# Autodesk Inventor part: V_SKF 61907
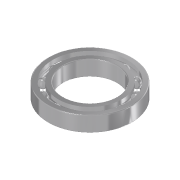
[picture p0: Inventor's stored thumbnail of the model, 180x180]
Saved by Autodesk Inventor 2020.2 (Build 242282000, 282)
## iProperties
+MSCProtocol1+ProtocolID: P00060228140304281
+MSCProtocol2+Protocol: P00060228140304281<@PID>[Version]<@EL>Version=2.2<@EL>[Files]<@EL>DataFile=SpiData|n024630a<@EL>[Synchronize]<@EL>ChangedVars=<@EL>[Calc]<@EL>DDmin=<@EL>DDmax=<
Manager: www.cadconsulting.pl
Company: Fabian Stasiak CAD Consulting
Shininess: 20.0
Length Units: 11269
Angle Units: 11279
Time Units: 11290
Mass Units: 11283
Length Display Precision: 3
Angle Display Precision: 2
Created: 2001-01
Part Number: V_SKF 61907
Material: Stal
Document SubType Name: Modeling
Description: Łożysko SKF 61907
Stock Number: SKF 61907
Project: Przekładnia X51
Designer: F.Stasiak
Density: 7.85 g/cm^3
Appearance: Chrom
Density: 7.86
Volumn: 47.63899704516156
Area: 199.2492810037185
PropertySet Name: Model Information
Control State: 0
Master: False
Checked Out: False
BOM1: Łożysko
BOM2: SKF 61907
Author: F.Stasiak
Subject: Zbiór ćwiczeń. Autodesk Inventor 2020. Kurs podstawowy
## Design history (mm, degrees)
node "Sketch1"
node "WorkPoint1"
sketch "Sketch2"
  geometry: L1 (17.5, 10)-(27.5, 10); L2 (17.5, 0)-(17.5, 10); L3 (27.5, 0)-(17.5, 0); L4 (27.5, 10)-(27.5, 0); L5 (0, 0)-(0, 20); L6 (0, 0)-(0, 20); L7 (-3.6, 0)-(46.8, 0) reference
  constraints: 12 end point, 3 vertical, 2 horizontal, 1 collinear, 1 other
  dimensions: "d1" = 35 diameter of L1.start L5 (= prf_d); "d3" = 55 diameter of L1.end L5 (= prf_dd); "d5" = 10 distance of L2.start L1.start (= msp_mdtd2)
revolve "RevolutionFull1" sketch "Sketch2" stored, may be unused: angle "d6" = 360 deg
node "WorkAxis1"
node "WorkPlane3"
sketch "Sketch3"
  geometry: L1 (24.3, 10)-(24.3, 7.4); L2 (20.7, 10)-(24.3, 10); L3 (20.7, 7.4)-(20.7, 10); L4 (20.7, 0)-(20.7, 2.6); L5 (24.3, 0)-(20.7, 0); L6 (24.3, 2.6)-(24.3, 0); L7 (27.5, 0)-(-27.5, 0) reference; L8 (27.5, 10)-(-27.5, 10) reference; L9 (0, -42.29)-(0, 61.29); L10 (0, 92.365)-(0, -52.649) reference; A1 r 3 centre (22.5, 5) between (24.3, 2.6) and (24.3, 7.4); A2 r 3 centre (22.5, 5) between (20.7, 7.4) and (20.7, 2.6)
  constraints: 14 end point, 4 collinear, 4 point on circle, 4 vertical, 2 centre point, 2 concentric, 2 horizontal, 2 point on line
  dimensions: "d9" = 6 diameter of A1 (= msp_mdtd6); "d21" = 20.7 distance between parallel lines of L9 L4 (= 0.5 x msp_d1); "d22" = 22.5 distance from line of L9 A1.centre (= 0.5 x msp_ds); "d23" = 24.3 distance between parallel lines of L9 L6 (= 0.5 x msp_dd1)
revolve "RevolutionFull2" sketch "Sketch3" stored, may be unused: angle "d10" = 360 deg
node "WorkPlane4"
node "Sketch4"
node "WorkPoint2"
revolve "RevolutionFull3" stored, may be unused: angle "d16" = 360 deg
pattern_circular "PolarAray1" dims "d17" = 116.5 (= msp_pocet), angle "d19" = 360 deg
fillet "Fillet1" dims "d20" = 0.6 (= prf_r)
node "Bryła1"
node "Korpusy bryłowe"
node "Korpusy powierzchniowe"
sketch "Sketch5"
  geometry: L1 (22.5, 2)-(22.5, 8); L2 (24.3, 0)-(-24.3, 0) reference; L3 (22.5, 2)-(22.5, 8); A1 r 3 centre (22.5, 5) between (22.5, 2) and (22.5, 8); A2 r 3 centre (22.5, 5) between (24.3, 2.6) and (24.3, 7.4) reference
  constraints: 4 end point, 2 point on circle, 1 centre point, 1 concentric, 1 vertical
  dimensions: "d13" = 0 horizontal distance of A1.centre L1.start; "d15" = 6.0001 diameter of A1 (computed from msp_mdtd6)
other parameters: "prf_d" = 35 [user parameter; used in 3 equation terms], "prf_dd" = 55 [user parameter; used in 3 equation terms], "prf_r" = 0.6 [user parameter; used in 1 equation term], "msp_ds" = 45 (= 0.5 x prf_d + 0.5 x prf_dd) [user parameter; used in 5 equation terms], "msp_d0" = 6 (= -0.3 x prf_d + 0.3 x prf_dd) [user parameter; used in 4 equation terms], "msp_d1" = 41.4 (= msp_ds - 0.6 x msp_d0) [user parameter; used in 1 equation term], "msp_dd1" = 48.6 (= msp_ds + 0.6 x msp_d0) [user parameter; used in 1 equation term], "msp_pom" = 67.5 (= 1.5 x msp_ds) [user parameter; used in 1 equation term], "msp_mdtd2" = 10 (= prf_b) [user parameter; used in 3 equation terms], "msp_mdtd4" = 45 (= msp_ds) [user parameter], "msp_mdtd6" = 6 (= msp_d0) [user parameter; used in 2 equation terms], "msp_mdtd7" = 5 (= 0.5 x msp_mdtd2) [user parameter], "msp_pocet" = 116.5 (computed from msp_d0, msp_pom) [user parameter; used in 1 equation term], "d2" = 72 (derived), "d4" = 19 (derived), "d7" = 0, "d8" = 15.6 (derived), "d12" = 0 (derived), "d14" = 15.6001 (derived), "d25" = 0
